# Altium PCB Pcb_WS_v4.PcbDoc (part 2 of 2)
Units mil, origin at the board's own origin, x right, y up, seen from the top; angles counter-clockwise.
Board outline 3890 x 3890 mil, 2 copper layers (Top Layer, Bottom Layer); 75 components, 61 nets, 248 pads, 370 vias.
Unrouted connection lines stored in the file: 31.
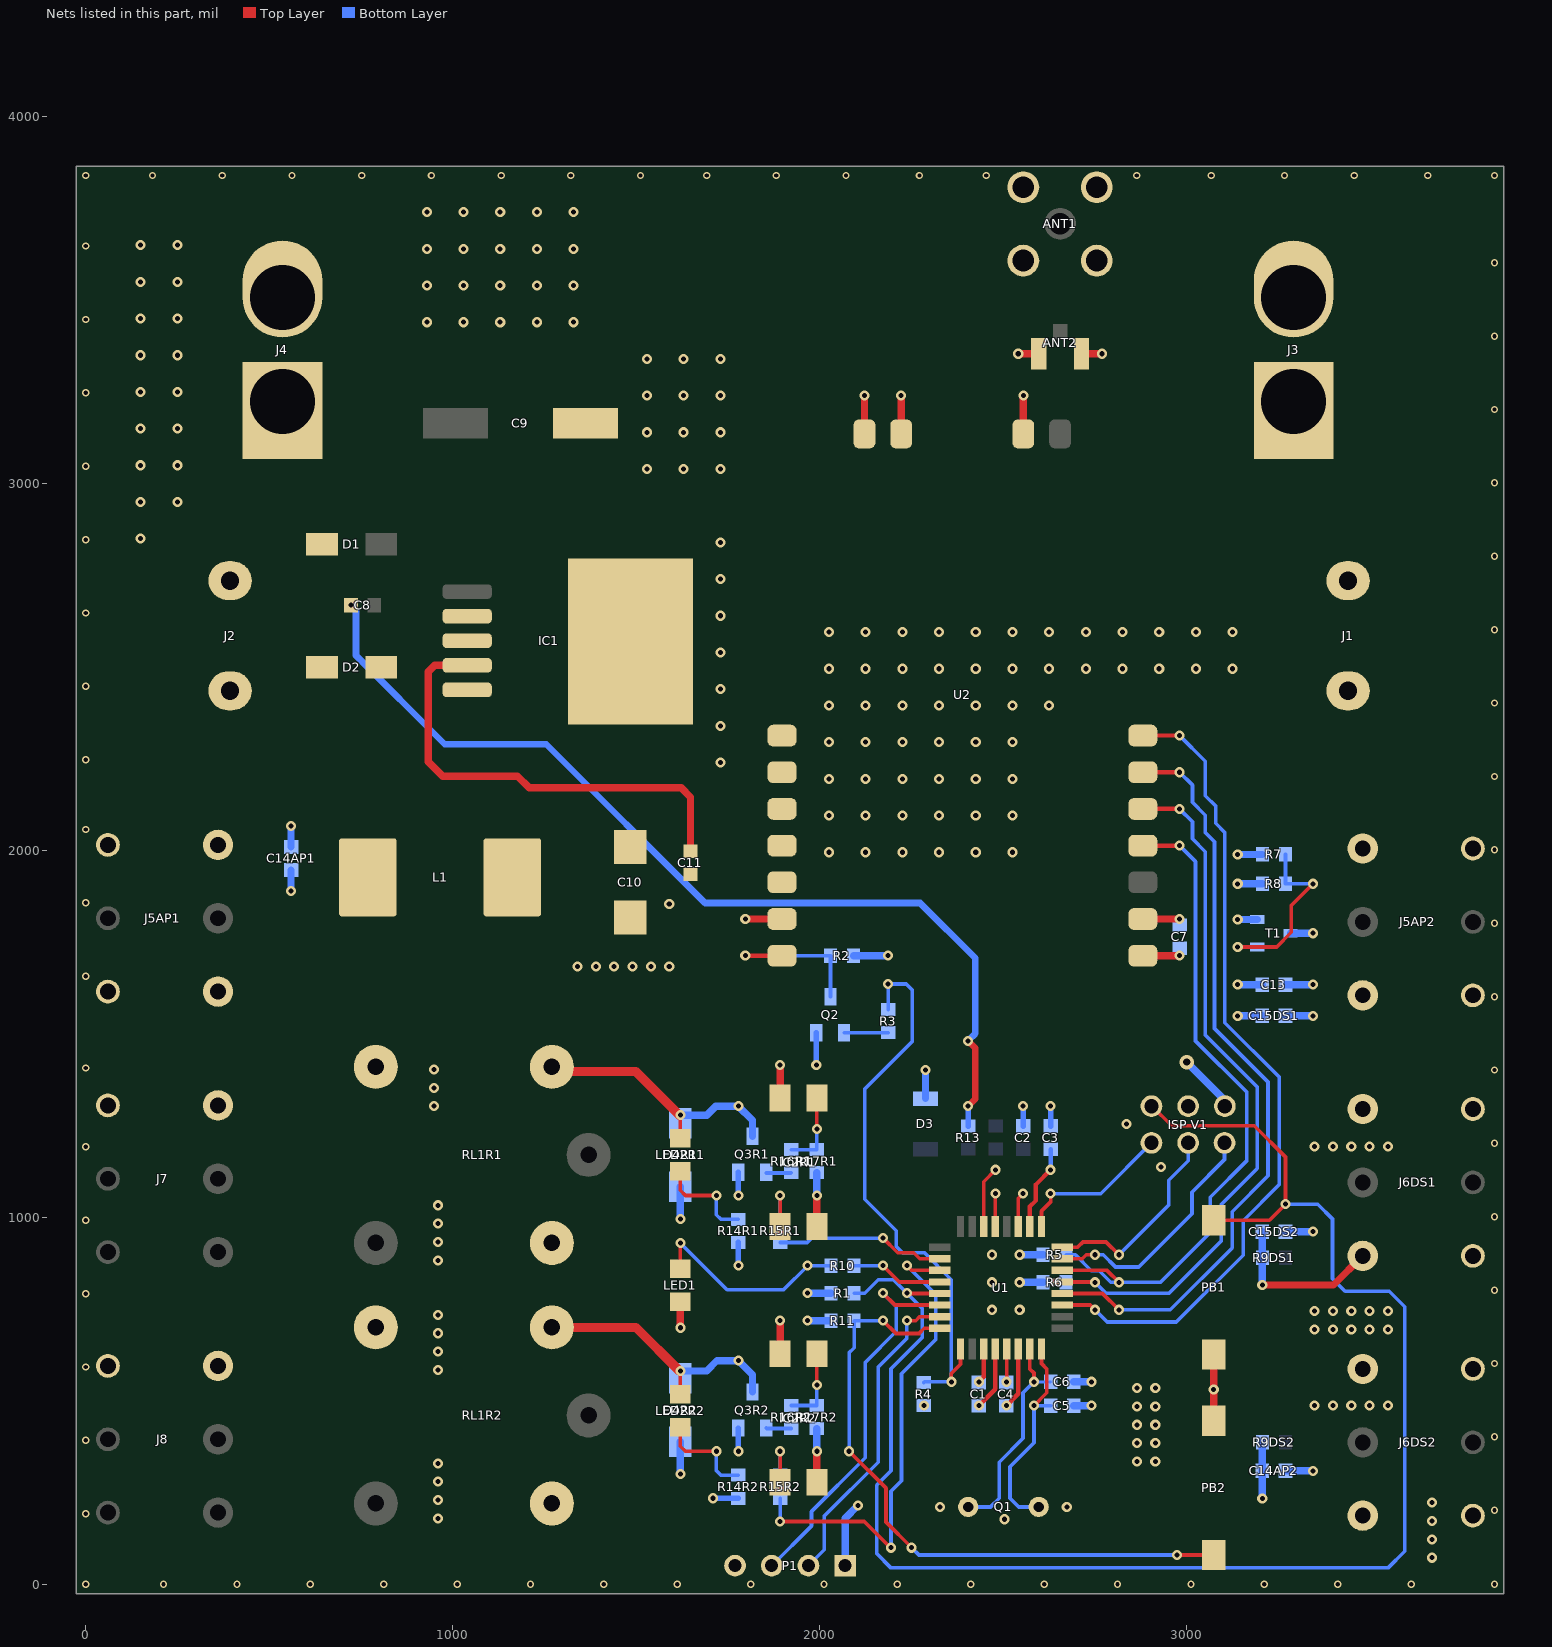
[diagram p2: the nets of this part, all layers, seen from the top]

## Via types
v1: diameter 27.56, hole 13.78, Top Layer to Bottom Layer, 293 vias
v2: diameter 20, hole 11.81, Top Layer to Bottom Layer, tented both sides, 76 vias
v3: diameter 39.37, hole 19.68, Top Layer to Bottom Layer, 1 vias

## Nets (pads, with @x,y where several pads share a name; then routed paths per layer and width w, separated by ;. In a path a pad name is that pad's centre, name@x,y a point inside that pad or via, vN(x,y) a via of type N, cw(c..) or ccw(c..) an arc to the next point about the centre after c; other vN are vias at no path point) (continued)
GND: "ISP V1.5" ANT1.2 ANT2.2 C1.2 C2.1 C3.2 C4.2 C5.2 C6.2 C7.2 C8.2 C9.2 C10.2 C11.2 C13.2 C14AP1.1 C14AP2.1 C15DS1.1 C15DS2.1 D2.2 D3.2 IC1.3 IC1.5 IC1.6 IC2R1.2 IC2R2.2 J2.1 J4.1 J5AP1.3 J5AP2.3 J6DS1.3 J6DS2.3 LED1.2 P1.4 PB1.2 PB2.2 Q2.2 Q3R1.2 Q3R2.2 R4.1 R5.2 R6.2 R7.1 R13.2 R17R1.1 R17R2.1 U1.3 U1.5 U1.21 U2.7 U2.9 U2.15 U2.16 U2.17 | length 5131
  Top Layer w9.84: U1.21@2479.06,975.59 2479.06,1064.06 v1(2480,1065) ; v1(2509.61,552.18) 2510.55,553.13 U1.5@2510.55,641.59
  Top Layer w12: v1(2434.61,552.18) 2447.56,565.13 U1.3@2447.56,641.59
  Top Layer w18: v1(2405,1303.39) 2425,1323.39 2425,1352.69 2425,1461 v1(2405,1481)
  Top Layer w20: v1(1620.86,699.46) LED1.2@1620.86,770 ; v1(1797.96,1813.49) U2.9@1897.96,1813.49 ; IC2R2.2@1992.86,278.06 v1(1992.86,362.87) ; IC2R1.2@1992.86,975.34 v1(1992.86,1060.15) ; U2.15@2122.76,3135.54 v1(2122.76,3240) ; U2.16@2222.76,3135.54 v1(2222.76,3240) ; v1(2541.92,3354) ANT2.2@2597.76,3354 ; U2.17@2555.84,3135.54 v1(2555.84,3240) ; ANT2.2@2713.91,3354 v1(2769.75,3354) ; U2.7@2881.43,1713.49 v1(2981.43,1713.49) ; PB2.2@3074.53,446.14 v1(3074.53,531.63) PB1.2@3074.53,626.54
  Bottom Layer w15: v1(1779.06,362.87) Q3R2.2@1779.06,426.1 ; v1(1779.06,1060.15) Q3R1.2@1779.06,1123.38 ; v1(1991.4,1416.07) Q2.2@1991.4,1503.58 ; R13.2@2405,1249.32 v1(2405,1303.39) ; C2.1@2555,1249.32 v1(2555,1303.39) ; C3.2@2630,1249.32 v1(2630,1303.39)
  Bottom Layer w18: v1(723,2669.78) 723,2668.46 737,2654.46 737,2531.74 978.74,2290 1255.5,2290 1688.5,1857 2274.34,1857 2425,1706.34 2425,1501.7 2405,1481.7 v1(2405,1481)
  Bottom Layer w20: C14AP1.1@560,2010 v1(560,2067.32) ; v1(1992.86,362.87) R17R2.1@1992.86,424.74 ; v1(1992.86,1060.15) R17R1.1@1992.86,1122.02 ; D3.2@2289.08,1324.12 v1(2289.08,1401.78) ; v1(2545.81,823.39) R6.2@2609.67,823.39 ; v1(2545.81,898.39) R5.2@2609.67,898.39 ; C5.2@2693.3,487.18 v1(2741.21,487.18) ; C6.2@2693.3,552.18 v1(2741.21,552.18) ; v1(3140,1549.46) C15DS1.1@3207.01,1549.46 ; v1(3140,1634.46) C13.2@3207.01,1634.46 ; v1(3140,1989.46) R7.1@3207.01,1989.46 ; C14AP2.1@3270,309.46 v1(3345,309.46) ; C15DS2.1@3270,961.31 v1(3345,961.31)
  other v1: 2504.75,177.52 960,180 2328.96,210.91 2674.14,211.33 960,230 960,280 960,330 2865.32,335.02 2915.32,335.02 2865.32,385.02 2915.32,385.02 2865.32,435.02 2915.32,435.02 2865.32,485.02 2915.32,485.02 2284.61,487.18 3349.51,487.18 3399.51,487.18 3449.51,487.18 3499.51,487.18 3549.51,487.18 2865.32,535.02 2915.32,535.02 960,584.51 960,634.51 960,684.51 3349.51,694.61 3399.51,694.61 3449.51,694.61 3499.51,694.61 3549.51,694.61 960,734.51 3349.51,744.61 3399.51,744.61 3449.51,744.61 3499.51,744.61 3549.51,744.61 2470.81,748.39 2545.81,748.39 2470.81,823.39 960,883.21 2470.81,898.39 960,933.21 960,983.21 960,1033.21 2931.35,1137.33 3349.51,1193.65 3399.51,1193.65 3449.51,1193.65 3499.51,1193.65 3549.51,1193.65 2836.6,1254.69 950,1303.39 950,1353.39 950,1403.39 1340.62,1683.72 1390.62,1683.72 1440.62,1683.72 1490.62,1683.72 1540.62,1683.72 1590.62,1683.72 1590.62,1854.25 2026.06,1995.48 2126.06,1995.48 2226.06,1995.48 2326.06,1995.48 2426.06,1995.48 2526.06,1995.48 2026.06,2095.48 2126.06,2095.48 2226.06,2095.48 2326.06,2095.48 2426.06,2095.48 2526.06,2095.48 2026.06,2195.48 2126.06,2195.48 2226.06,2195.48 2326.06,2195.48 2426.06,2195.48 2526.06,2195.48 1730,2240 2026.06,2295.48 2126.06,2295.48 2226.06,2295.48 2326.06,2295.48 2426.06,2295.48 2526.06,2295.48 1730,2340 2026.06,2395.48 2126.06,2395.48 2226.06,2395.48 2326.06,2395.48 2426.06,2395.48 2526.06,2395.48 2626.06,2395.48 1730,2440 2026.06,2495.48 2126.06,2495.48 2226.06,2495.48 2326.06,2495.48 2426.06,2495.48 2526.06,2495.48 2626.06,2495.48 2726.06,2495.48 2826.06,2495.48 2926.06,2495.48 3026.06,2495.48 3126.06,2495.48 1730,2540 2026.06,2595.48 2126.06,2595.48 2226.06,2595.48 2326.06,2595.48 2426.06,2595.48 2526.06,2595.48 2626.06,2595.48 2726.06,2595.48 2826.06,2595.48 2926.06,2595.48 3026.06,2595.48 3126.06,2595.48 1730,2640 1730,2740 1730,2840 150,2850 150,2950 250,2950 1530,3040 1630,3040 1730,3040 150,3050 250,3050 1530,3140 1630,3140 1730,3140 150,3150 250,3150 1530,3240 1630,3240 1730,3240 150,3250 250,3250 1530,3340 1630,3340 1730,3340 150,3350 250,3350 930,3440 1030,3440 1130,3440 1230,3440 1330,3440 150,3450 250,3450 930,3540 1030,3540 1130,3540 1230,3540 1330,3540 150,3550 250,3550 930,3640 1030,3640 1130,3640 1230,3640 1330,3640 150,3650 250,3650 930,3740 1030,3740 1130,3740 1230,3740 1330,3740
  other v2: 0,0 212.5,0 412.5,0 612.5,0 812.5,0 1012.5,0 1212.5,0 1412.5,0 1612.5,0 1812.5,0 2012.5,0 2212.5,0 2412.5,0 2612.5,0 2812.5,0 3012.5,0 3212.5,0 3412.5,0 3612.5,0 3840,0 0,192.5 3840,202 0,392.5 3840,402 0,592.5 3840,602 0,792.5 3840,802 0,992.5 3840,1002 0,1192.5 3840,1202 3840,1402 0,1407.5 3840,1602 0,1657.5 3840,1802 0,1857.5 3840,2002 0,2057.5 3840,2202 0,2247.5 3840,2402 0,2447.5 3840,2602 0,2647.5 3840,2802 0,2847.5 3840,3002 0,3047.5 3840,3202 0,3247.5 3840,3402 0,3447.5 3840,3602 0,3647.5 0,3840 182.5,3840 372.5,3840 562.5,3840 752.5,3840 942.5,3840 1132.5,3840 1322.5,3840 1512.5,3840 1692.5,3840 1882.5,3840 2072.5,3840 2272.5,3840 2455,3840 2865,3840 3067.5,3840 3267.5,3840 3457.5,3840 3657.5,3840 3840,3840
GND-SOLAR: J1.2 J3.1
LED: R10.1 U1.28 | length 251.5
  Top Layer w10: v1(2173.39,868.79) 2217.84,824.34 U1.28@2327.8,824.34
  Bottom Layer w10: R10.1@2094.71,868.79 v1(2173.39,868.79)
M0: U1.11 U2.1 | length 2257
  Top Layer w10: U1.11@2661.8,761.35 2738.26,761.35 v1(2751.21,748.39)
  Top Layer w12: U2.1@2881.43,2313.49 v1(2981.43,2313.49)
  Bottom Layer w10: v1(2751.21,748.39) 2784.61,715 2972.76,715 3155,897.24 3155,991.44 3252.78,1089.22 3252.78,1383.22 3105,1531 3105,2049.32 3079.99,2074.33 3079.99,2121.3 3051.66,2149.62 3051.66,2243.26 v1(2981.43,2313.49)
M1: U1.12 U2.2 | length 2088.2
  Top Layer w10: U1.12@2661.8,792.84 2771.76,792.84 v1(2816.21,748.39)
  Top Layer w12: U2.2@2881.43,2213.49 v1(2981.43,2213.49)
  Bottom Layer w10: v1(2816.21,748.39) 2956.3,748.39 3125,917.1 3125,1015.78 3222.63,1113.4 3222.63,1369.3 3076.84,1515.08 3076.84,2024.15 3051.66,2049.32 3051.66,2096.29 3016.54,2131.41 3016.54,2178.37 v1(2981.43,2213.49)
MISO: "ISP V1.2" U1.16 | length 558.1
  Top Layer w10: U1.16@2661.8,918.83 2703.65,918.83 2718.21,933.39 2781.21,933.39 v1(2816.21,898.39)
  Bottom Layer w10: v1(2816.21,898.39) 2951.74,1033.92 2951.74,1101.42 3005,1154.68 3005,1203.39
MOSI: "ISP V1.3" U1.15 | length 662
  Top Layer w10: U1.15@2661.8,887.33 2716.13,887.33 2727.19,898.39 v1(2751.21,898.39)
  Bottom Layer w10: v1(2751.21,898.39) 2773.31,898.39 2806.71,865 2870.12,865 3015.32,1010.2 3015.32,1069.12 3104,1157.81 3104,1203.39
NetD2_1: D2.1 IC1.2 L1.1
NetD4R1_2: D4R1.2 LED2R1.2 Q3R1.3 RL1R1.4 | length 728.5
  Top Layer w10: LED2R1.2@1620.86,1215.54 v1(1620.86,1278.81)
  Top Layer w25: RL1R1.4@1270.86,1397.82 1499.46,1397.82 v1@1618.47,1278.81
  Bottom Layer w20: D4R1.2@1618.47,1278.81 v1(1620.86,1278.81) 1692.53,1278.81 1717.12,1303.39 v1(1779.06,1303.39) 1817.66,1264.8 Q3R1.3@1817.66,1221.8
NetD4R2_2: D4R2.2 LED2R2.2 Q3R2.3 RL1R2.4 | length 734
  Top Layer w10: LED2R2.2@1620.86,518.26 v1(1620.86,581.53)
  Top Layer w25: RL1R2.4@1270.86,700.54 1499.46,700.54 v1@1618.47,581.53
  Bottom Layer w20: D4R2.2@1618.47,581.53 1692.53,581.53 1721,610 v1(1779.06,610) 1817.66,571.4 Q3R2.3@1817.66,524.52
NetIC2R1_1: IC2R1.1 R15R1.2 | length 149.9
  Top Layer w10: IC2R1.1@1892.86,975.34 v1(1892.86,1060.15)
  Bottom Layer w10: R15R1.2@1892.86,995.01 v1(1892.86,1060.15)
NetIC2R2_1: IC2R2.1 R15R2.2 | length 149.9
  Top Layer w10: IC2R2.1@1892.86,278.06 v1(1892.86,362.87)
  Bottom Layer w10: R15R2.2@1892.86,297.73 v1(1892.86,362.87)
NetLED1_1: LED1.1 R10.2 | length 561.5
  Top Layer w10: LED1.1@1620.86,860 v1(1620.86,930.54)
  Bottom Layer w10: v1(1620.86,930.54) 1748.4,803 1902.07,803 v1(1967.86,868.79) R10.2@2031.72,868.79
NetLED2R1_1: LED2R1.1 R14R1.2 | length 273.2
  Top Layer w10: LED2R1.1@1620.86,1125.54 1620.86,1074.14 1634.86,1060.15 v1(1719.06,1060.15)
  Bottom Layer w10: v1(1719.06,1060.15) 1719.06,1007.6 1731.65,995.01 R14R1.2@1779.06,995.01
NetLED2R2_1: LED2R2.1 R14R2.2 | length 273.2
  Top Layer w10: LED2R2.1@1620.86,428.26 1620.86,376.86 1634.86,362.87 v1(1719.06,362.87)
  Bottom Layer w10: v1(1719.06,362.87) 1719.06,310.32 1731.65,297.73 R14R2.2@1779.06,297.73
NetQ2_1: Q2.1 R3.2 | length 119.9
  Bottom Layer w10: Q2.1@2067.2,1503.8 R3.2@2187.06,1503.8
NetQ3R1_1: Q3R1.1 R16R1.2 | length 68.4
  Bottom Layer w10: Q3R1.1@1854.86,1121.01 1921.85,1121.01 R16R1.2@1922.86,1122.02
NetQ3R2_1: Q3R2.1 R16R2.2 | length 68.7
  Bottom Layer w10: Q3R2.1@1854.86,426.31 1856.43,424.74 R16R2.2@1922.86,424.74
NetR7_2: R7.2 R8.2 T1.1 | length 527.4
  Top Layer w10: v1(3140,1737.33) 3246.14,1737.33 3286.13,1777.32 3286.13,1850.59 v1(3345,1909.46)
  Bottom Layer w10: v1(3140,1737.33) T1.1@3193.23,1737.33 ; R7.2@3270,1989.46 R8.2@3270,1909.46 v1(3345,1909.46)
NetU1_19: U1.19 | length 94.8
  Top Layer w10: U1.19@2542.05,975.59 2542.05,1052.05 v1(2555,1065)
NetU1_22: U1.22 | length 167.8
  Top Layer w10: U1.22@2447.56,975.59 2447.56,1097.56 v1(2480,1130)
NetU2_10: U2.10
NetU2_11: U2.11
NetU2_12: U2.12
NetU2_13: U2.13
NetU2_14: U2.14
OPEN1: J7.1 RL1R1.3
OPEN2: J8.1 RL1R2.3
P5V-Main: "ISP V1.6" C1.1 C3.1 C4.1 C7.1 C10.1 C11.1 D4R1.1 D4R2.1 IC1.4 IC2R1.4 IC2R2.4 L1.2 P1.1 R1.1 R2.2 R8.1 R11.1 R14R1.1 R14R2.1 RL1R1.5 RL1R2.5 T1.2 U1.4 U1.6 U1.18 U2.6 | length 3107.7
  Top Layer w12: v1(2434.61,487.18) 2479.06,531.63 U1.4@2479.06,641.59 ; v1(2509.61,487.18) 2542.05,519.62 U1.6@2542.05,641.59 ; U1.18@2573.54,975.59 2573.54,1029.92 2590,1046.38 2590,1090 v1(2630,1130)
  Top Layer w20: IC1.4@1040.04,2505.03 952.03,2505.03 934,2487 934,2242.02 973.02,2203 1177,2203 1209.23,2170.77 1623.39,2170.77 1648.55,2145.61 C11.1@1648.55,1998.5 ; IC2R2.4@1892.86,628.46 v1(1892.86,718.79) ; IC2R1.4@1892.86,1325.74 v1(1892.86,1416.07) ; U2.6@2881.43,1813.49 v1(2981.43,1813.49)
  Bottom Layer w12: v1(2630,1130) C3.1@2630,1186.32
  Bottom Layer w15: v1(1710,234.74) R14R2.1@1779.06,234.74 ; v1(1779.06,868.79) R14R1.1@1779.06,932.02
  Bottom Layer w20: v1(1620.86,300.47) D4R2.1@1620.86,388.39 ; v1(1620.86,996.01) D4R1.1@1620.86,1083.93 ; v1(1967.86,718.79) R11.1@2031.72,718.79 ; v1(1967.86,793.79) R1.1@2031.72,793.79 ; P1.1@2070,51 2070,180.55 v1(2105,215.55) ; R2.2@2092.99,1713.49 v1(2187.06,1713.49) ; v3(3001.21,1423.39) 3105,1319.6 3105,1303.39 ; v1(3140,1812.14) T1.2@3193.23,1812.14 ; v1(3140,1909.46) R8.1@3207.01,1909.46
P5V-SEN: C13.1 C14AP1.2 C14AP2.2 C15DS1.2 C15DS2.2 J5AP1.1 J5AP2.1 J6DS1.1 J6DS2.1 R9DS1.2 R9DS2.2 T1.3 | length 873.8
  Top Layer w20: v1(3207.01,815.77) 3401.09,815.77 J6DS1.1@3480.86,895.54
  Bottom Layer w20: v1(560,1889.69) C14AP1.2@560,1947.01 ; v1(3207.01,234.46) C14AP2.2@3207.01,309.46 R9DS2.2@3207.01,387.26 ; v1(3207.01,815.77) R9DS1.2@3207.01,890.77 C15DS2.2@3207.01,961.31 ; C15DS1.2@3270,1549.46 v1(3345,1549.46) ; C13.1@3270,1634.46 v1(3345,1634.46) ; T1.3@3283.78,1774.74 v1(3345,1774.74)
  other v1: 3670,72.74 3670,122.74 3670,172.74 3670,222.74
P12V-BAT: D1.2 J2.2 J4.2
P16V-SOLAR: J1.1 J3.2
RESET-E32: R3.1 R4.2 U1.1 | length 1571.2
  Top Layer w10: v1(2359.61,552.18) 2359.61,574.79 2384.57,599.75 U1.1@2384.57,641.59
  Bottom Layer w9.84: R3.1@2187.06,1566.79 v1(2187.06,1636.26)
  Bottom Layer w10: v1(2187.06,1636.26) 2236.59,1636.26 2252.53,1620.32 2252.53,1478.75 2123.79,1350.01 2123.79,1049.97 2209.61,964.15 2209.61,920.77 2226.6,903.79 2286.16,903.79 2359.61,830.34 v1(2359.61,552.18) 2286.61,552.18 R4.2@2284.61,550.17
RL-CT-QR1: IC2R1.3 R16R1.1 R17R1.2 | length 210.7
  Top Layer w10: v1(1992.86,1240.93) IC2R1.3@1992.86,1325.74
  Bottom Layer w10: R16R1.1@1922.86,1185.01 R17R1.2@1992.86,1185.01 v1(1992.86,1240.93)
RL-CT-QR2: IC2R2.3 R16R2.1 R17R2.2 | length 210.7
  Top Layer w10: v1(1992.86,543.65) IC2R2.3@1992.86,628.46
  Bottom Layer w10: R16R2.1@1922.86,487.73 R17R2.2@1992.86,487.73 v1(1992.86,543.65)
RL-CTL1: R15R1.1 U1.26 | length 463.2
  Top Layer w10: v1(2173.39,943.79) 2213.39,903.79 2257.02,903.79 2273.48,887.33 U1.26@2327.8,887.33
  Bottom Layer w10: R15R1.1@1892.86,932.02 1966.67,932.02 1978.44,943.79 v1(2173.39,943.79)
RL-CTL2: R15R2.1 U1.27 | length 1341.3
  Top Layer w10: v1(1892.86,171.51) 2122.09,171.51 2193.6,100 v1(2195,100) ; v1(2238.39,868.79) 2251.35,855.83 U1.27@2327.8,855.84
  Bottom Layer w10: v1(1892.86,171.51) R15R2.1@1892.86,234.74 ; v1(2195,100) 2195,253.8 2223.78,282.58 2223.78,573.78 2316.63,666.63 2316.63,790.55 v1(2238.39,868.79)
RST-E32: Q2.3 R2.1 U2.8 | length 443.5
  Top Layer w12: v1(1797.96,1713.49) U2.8@1897.96,1713.49
  Bottom Layer w10: v1(1797.96,1713.49) R2.1@2030,1713.49 Q2.3@2030,1602.01
RST_MCU: "ISP V1.4" PB1.1 R1.2 U1.29 | length 4483.3
  Top Layer w10: v1(2238.39,793.79) 2239.34,792.84 U1.29@2327.8,792.84 ; 2905,1303.39 2906.61,1303.39 2960,1250 3185,1250 3270,1165 v1(3270,1036.31) 3226.37,992.69 PB1.1@3074.53,992.69
  Bottom Layer w10: R1.2@2094.71,793.79 2123.79,793.79 2160,830 2202.18,830 v1(2238.39,793.79) 2279.79,752.39 2279.79,672.4 2195,587.61 2195,309.71 2155.91,270.62 2155.91,84.09 2195,45 3549.61,45 3595.18,90.57 3595.18,756.82 3553.32,798.68 3432.64,798.68 3398.54,832.78 3398.54,996 3358.23,1036.31 v1(3270,1036.31)
RXD-E32: R6.1 U1.13 U2.3 | length 1989.3
  Top Layer w10: U1.13@2661.8,824.34 2750.27,824.34 v1(2751.21,823.39)
  Top Layer w12: U2.3@2881.43,2113.49 v1(2981.43,2113.49)
  Bottom Layer w10: R6.1@2672.66,823.39 v1(2751.21,823.39) 2780.82,793.79 2952.86,793.79 3095,935.92 3095,1035.54 3193.23,1133.77 3193.23,1355.88 3051.66,1497.45 3051.66,1997.11 3016.54,2032.22 3016.54,2078.37 v1(2981.43,2113.49)
RXM: P1.3 U1.30 | length 1066.3
  Top Layer w10: v1(2173.39,793.79) 2205.84,761.35 U1.30@2327.8,761.35
  Bottom Layer w10: P1.3@1870,51 1978.44,159.44 1978.44,198.44 2125,345 2125,605 2209.61,689.61 2209.61,757.57 v1(2173.39,793.79)
SCK: "ISP V1.1" U1.17 | length 432.1
  Top Layer w10: U1.17@2605.04,975.59 2605.04,1017.43 2630,1042.39 v1(2630,1065)
  Bottom Layer w10: v1(2630,1065) 2766.61,1065 2905,1203.39
TXD-E32: R5.1 U1.14 U2.4 | length 1919.5
  Top Layer w10: U1.14@2661.8,855.84 2783.77,855.83 v1(2816.21,823.39)
  Top Layer w12: U2.4@2881.43,2013.49 v1(2981.43,2013.49)
  Bottom Layer w10: R5.1@2672.66,898.39 2697.59,898.39 2740.98,855 2762.28,855 2793.89,823.39 v1(2816.21,823.39) 2929.61,823.39 3065,958.79 3065,1055 3165,1155 3165,1341 3025,1481 3025,1969.92 v1(2981.43,2013.49)
TXM: P1.2 U1.31 | length 873
  Top Layer w10: v1(2238.39,718.79) 2262.41,718.79 2273.48,729.85 U1.31@2327.8,729.85
  Bottom Layer w10: P1.2@1970,51 2013.25,94.25 2013.25,186.2 2160,332.95 2160,592.5 2238.39,670.89 v1(2238.39,718.79)
WAKE: PB2.1 R11.2 U1.32 | length 1780.3
  Top Layer w10: v1(2080.83,362.87) 2181.2,262.5 2181.2,170.15 v1(2251.35,100) ; v1(2173.39,718.79) 2208.39,683.79 2271.39,683.79 2285.96,698.35 U1.32@2327.8,698.35 ; v1(2975,80) PB2.1@3074.53,80
  Bottom Layer w10: v1(2080.83,362.87) 2080.83,631.12 2094.71,645 R11.2@2094.71,718.79 v1(2173.39,718.79) ; v1(2251.35,100) 2271.35,80 v1(2975,80)
XTAL1: C6.1 Q1.1 U1.7 | length 590.6
  Top Layer w10: U1.7@2573.54,641.59 2573.54,587.26 2584.61,576.2 v1(2584.61,552.18)
  Bottom Layer w8: v1(2584.61,552.18) C6.1@2630.31,552.18
  Bottom Layer w10: Q1.1@2405.49,211.12 2466.32,211.12 2489.95,234.74 2489.95,333.04 2555,398.09 2555,522.58 v1(2584.61,552.18)
XTAL2: C5.1 Q1.2 U1.8 | length 587.9
  Top Layer w10: v1(2584.61,487.18) 2619.61,522.18 2619.61,587.26 2605.04,601.83 U1.8@2605.04,641.59
  Bottom Layer w10: Q1.2@2597.61,211.12 2543.17,211.12 2519.55,234.74 2519.55,320.77 2584.61,385.83 v1(2584.61,487.18) C5.1@2630.31,487.18

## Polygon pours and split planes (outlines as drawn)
GND on Top Layer "GND_L01_P040" (solid, pour order 40): 770,1271.63 900,1141.63 900,969.62 900,10 1030,10 1030,1470 539.28,1470 460.95,1551.25 460.95,1730 10,1730 10,1403.39 508.23,1403.39 640,1271.63
GND on Top Layer "GND_L01_P039" (solid, pour order 39): 2906.03,595.06 2712.18,595.06 2712.18,295 2960,295 3830,295 3830,2213.49 3175,2213.49 3175,2650 1975,2650 1975,1943 3216,1943 3216,1788 3076.84,1788 3076.84,1395.95 2816.21,1395.95 2816.21,1106.63 2906.03,1106.63
P5V-Main on Top Layer "P5V-MAIN_L01_P035" (solid, pour order 35): 2905,595.06 2711.81,595.06 2711.81,295 2632.31,295 2405.49,295 2405.49,151.44 1162.95,151.44 1162.95,1575 1295,1575 1295,1625 1634.86,1625 1634.86,1875 1690,1875 1690,1929.85 3216,1929.85 3216,1788 3076.84,1788 3076.84,1395.95 2799.07,1395.95 2799.07,1106.63 2905,1106.63
P5V-SEN on Top Layer "P5V-SEN_L01_P031" (solid, remove dead copper, pour order 31): 2597.61,267.76 2597.61,125 2150,125 2123.56,151.44 1162.95,151.44 1162.95,1575 590.98,1575 590.98,2085 565.99,2110 55,2110 15,2070 15,1947.49 35.49,1927 423.78,1927 459.78,1891 459.78,1552.12 541.9,1470 960,1470 1030,1400 1030,35.49 2121.6,35.49 2147.09,10 2950,10 2950,135.48 2995.48,135.48 3139.52,135.48 3139.52,10 3265,10 3830,10 3830,267.76
GND on Top Layer "GND_L01_P037" (solid, pour order 37): 1975,3804.51 1975,2750 3000,2750 3000,3804.51
GND on Top Layer "GND_L01_P027" (solid, remove dead copper, pour order 27): 1690,1875 1690,1967 1825,1967 1825,2650 1875,2650 1875,3830 10,3830 10,2225 625,2225 625,1625 1625,1625 1625,1875
GND-SOLAR on Top Layer "GND-SOLAR_L01_P028" (solid, pour order 28): 3275,2750 3100,2750 3100,3830 3830,3830 3830,2285 3275,2285
no net on Top Layer "Top Layer-No Net" (solid, shelved, pour order 14): 1035.77,4959.95
no net on Top Layer "AutoNaming" (solid, shelved, pour order 22): -54.14,125.54
no net on Top Layer "AutoNaming" (solid, shelved, pour order 26): -54.14,125.54
GND on Bottom Layer "GND-Bottom" (solid, remove dead copper, pour order 38): 10,3830 1875,3830 1875,2650 3175,2650 3175,2215 3830,2215 3830,1805.54 3340.37,1805.54 3340.37,1402 3605,1402 3605,261.82 3605,10 10,10
P5V-SEN on Bottom Layer "P5V-SEN_L02_P030" (solid, remove dead copper, pour order 30): 3340.37,1414.51 3352.88,1402 3585.35,1402 3605,1382.35 3605,311.82 3605,10 3820,10 3820,1655 3805,1670 3407.69,1670 3392.69,1685 3392.69,1805.54 3340.37,1805.54
GND on Bottom Layer "GND_L02_P033" (solid, pour order 33): 1975,3804.51 1975,2750 3000,2750 3000,3804.51
P16V-SOLAR on Bottom Layer "P16V-SOLAR_L02_P029" (solid, pour order 29): 3275,2750 3100,2750 3100,3837.5 3837.5,3837.5 3837.5,2285 3275,2285

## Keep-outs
Bottom Layer:
  region: 3839.91,2216.96
Keep-Out Layer:
  the board outline again, w5

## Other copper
Top Layer:
  pour cut-out: 3040.36,489.6 3108,489.6 3108,402.6 3040.36,402.6
  pour cut-out: 3040.36,670 3108,670 3108,583 3040.36,583
  pour cut-out: 2921.04,1743.27 2921.04,1683.72 2841.81,1683.72 2841.81,1743.27
  region net GND: 2654.54,280.26 2668.29,274.56 2680.67,266.29 2691.2,255.77 2699.47,243.39 2705.17,229.63 2708.07,215.03 2708.07,207.58 2708.07,200.83 2705.44,187.58 2700.27,175.1 2692.76,163.86 2683.21,154.31 2671.97,146.81 2659.49,141.64 2646.24,139 2362.87,139 2348.35,141.89 2334.67,147.55 2322.37,155.78 2311.9,166.24 2303.68,178.55 2298.01,192.23 2295.12,206.74 2295.12,214.15 2295.12,220.94 2297.78,234.28 2302.98,246.84 2310.53,258.14 2320.15,267.76 2331.45,275.31 2344.01,280.51 2357.35,283.17 2639.93,283.17 hole: 2597.61,249 2587.81,247.71 2578.67,243.93 2570.83,237.91 2564.81,230.06 2561.02,220.92 2559.73,211.12 2561.02,201.31 2564.81,192.18 2570.83,184.33 2578.67,178.31 2587.81,174.53 2597.61,173.24 2607.42,174.53 2616.56,178.31 2624.4,184.33 2630.42,192.18 2634.21,201.31 2635.5,211.12 2634.21,220.92 2630.42,230.06 2624.4,237.91 2616.56,243.93 2607.42,247.71 hole: 2405.49,249 2395.68,247.71 2386.55,243.93 2378.7,237.91 2372.68,230.06 2368.9,220.92 2367.61,211.12 2368.9,201.31 2372.68,192.18 2378.7,184.33 2386.55,178.31 2395.68,174.53 2405.49,173.24 2415.29,174.53 2424.43,178.31 2432.28,184.33 2438.3,192.18 2442.08,201.31 2443.37,211.12 2442.08,220.92 2438.3,230.06 2432.28,237.91 2424.43,243.93 2415.29,247.71
  region net GND: 2385,920 2385,698.35 2605.04,698.35 2605.04,918.83
  pour cut-out: 2575,3400 2736.22,3400 2736.22,3309.04 2575,3309.04
  pour cut-out: 2526.06,3175.16 2585.61,3175.16 2585.61,3095.92 2526.06,3095.92
  pour cut-out: 2192.99,3175.16 2252.54,3175.16 2252.54,3095.92 2192.99,3095.92
  pour cut-out: 2092.99,3175.16 2152.54,3175.16 2152.54,3095.92 2092.99,3095.92
  pour cut-out: 2921.04,1843.27 2921.04,1783.72 2841.81,1783.72 2841.81,1843.27
  pour cut-out: 2880,1855
  pour cut-out: 2880,1855
  pour cut-out: 2359.57,943.83 2630.04,943.83 2630.04,673.35 2359.57,673.35
  pour cut-out: 1849.32,329.48 2036.4,329.48 2036.4,226.65 1849.32,226.65
  pour cut-out: 2036.4,1377.15 2036.4,1274.32 1855,1274.32 1855,1377.15
  pour cut-out: 1578.36,1255.54 1663.36,1255.54 1663.36,1085.54 1578.36,1085.54
  pour cut-out: 1578.36,900 1663.36,900 1663.36,730 1578.36,730
  pour cut-out: 1663.36,558.26 1578.36,558.26 1578.36,388.26 1663.36,388.26
  pour cut-out: 2036.4,577.04 2036.4,679.87 1855,679.87 1855,577.04
  pour cut-out: 2584.61,472.76 2584.61,552.18 2345.19,552.18 2345.19,472.76
  pour cut-out: 2158.98,718.79 2238.39,718.79 2238.39,958.21 2158.98,958.21
  pour cut-out: 2830.63,898.39 2751.21,898.39 2751.21,658.97 2830.63,658.97
  pour cut-out: 2405,1144.42 2405,1065 2644.42,1065 2644.42,1144.42
  pour cut-out: 2359.57,943.83
  region net BAT-VSEN: 760,2647.5 769.5,2638 880,2638 927,2685 1102.5,2685 1115,2697.5 1115,3217.01 1092.01,3240 828.72,3240 760,3171.28 760,2920 734.51,2894.51 734.51,2762.55 760,2737.06
  region net P12V-BAT: 265,2844.68 360.86,2940.54 360.86,3332.7 393.16,3365 684.8,3365 734.51,3315.29 734.51,2943.37 707.5,2916.36 707.5,2765.64 683.42,2741.55 580.99,2741.55 536.41,2696.98 536.41,2639.22 505.56,2608.38 306.95,2608.38 265,2650.33
  pour cut-out: 855,2157 1075,2157 1295,2157 1295,1625 665,1625 665,2157
  pour cut-out: 752.21,2386.28 752.21,2735 1140.49,2735 1140.49,2386.28
  region net P5V-Main: 1075,1815 1095,1795 1175,1795 1295,1795 1335,1835 1335,1915 1365,1945 1405,1945 1555,1945 1585,1975 1807.96,1975 1817.96,1985 1817.96,2085 1807.96,2095 1132.5,2095 1075,2037.5 1075,2015.54
  region net NetD2_1: 932,2660 1101,2660 1108.75,2652.25 1108.75,2624.75 1102,2618 963,2618 901,2556 901,2203 855,2157 855,1825 840,1810 690,1810 665,1835 665,2205.55 750,2290.55 750,2598.75 769.25,2618 890,2618
  region net GND: -10,-10 3850,-10.18 3850,3850.04 2865,3850 2865,3830 3830,3830 3830,10 10,10 10,3830 2455,3830 2455,3850 -10,3850
  region: -25,3865
  region: 957.01,1081.11
  pour cut-out: 3895.54,1395.95
  pour cut-out: 3895.54,1395.95
  region: 285.86,2865.54
Bottom Layer:
  pour cut-out: 3174.29,421.95 3302.72,421.95 3302.72,274.78 3173.31,274.78
  pour cut-out: 525.32,2043.7 525.32,1925 590.98,1925 590.98,2043.7
  pour cut-out: 2596.61,586.86 2596.61,452.49 2766.4,452.49 2766.4,586.86
  pour cut-out: 1999,943.79 2127.43,943.79 2127.43,684.1 1999,684.1
  pour cut-out: 2946.74,1685 3004.61,1685 3004.61,1830.2 2946.74,1830.2
  pour cut-out: 625,1475 898.39,1475 898.39,1240.93 1435,1240.93 1435,1095 910,1095 910,530.93 1435,530.93 1435,385 910,385 910,10 10,10 10,1385 625,1385
  pour cut-out: 2705.38,788.71 2520.32,788.71 2520.32,933.08 2705.38,933.08
  pour cut-out: 2664.68,1152.62 2664.68,1324.59 2370.32,1324.59 2370.32,1152.62
  pour cut-out: 2333.52,1294.43 2244.7,1294.43 2244.7,1419.61 2333.52,1419.61
  pour cut-out: 2027.54,1034.66 1957.54,1034.66 1957.54,1217.73 2027.54,1217.73
  pour cut-out: 1805.79,1130 1805.79,1037.2 1752.33,1037.2 1752.33,1157 1805.79,1157
  pour cut-out: 3175.39,856.09 3302.72,856.09 3302.72,996 3175.39,996
  pour cut-out: 2020,1515 2020,1393.13 1964.67,1393.13 1964.67,1537.2 2020,1537.2
  pour cut-out: 1805.79,464.93 1805.79,339.93 1752.33,339.93 1752.33,464.93
  pour cut-out: 2027.54,520.45 2027.54,337.38 1957.54,337.38 1957.54,520.45
  pour cut-out: 3299.51,1669.15 3299.51,1514.78 3125.39,1514.78 3125.39,1669.15
  pour cut-out: 3302.72,2024.15 3302.72,1874.78 3125.39,1874.78 3125.39,2024.15
  pour cut-out: 2539.29,453.48 2242.62,453.48 2242.62,578.87 2539.29,578.87
  region net CLOSE1: 650,965 700,1015 862.6,1015 875,1002.6 875,865 865,855 34,855 21.5,867.51 21.5,955 31.5,965
  region net OPEN1: 33,1385 525,1385 615,1475 865,1475 875,1465 875,1335 865,1325 625,1325 545,1245 33,1245 22,1256 22,1374
  region net COM1: 30.75,1165 578.58,1165 654.51,1240.93 1415.87,1240.93 1435,1221.8 1435,1108.54 1421.46,1095 663.57,1095 613.58,1045 35,1045 20,1060 20,1154.25
  region net GND: -10,-10 3850,-10.18 3850,3850.04 2865,3850 2865,3830 3830,3830 3830,10 10,10 10,3830 2455,3830 2455,3850 -10,3850
  region net COM2: 30.75,455 578.58,455 654.51,530.93 1415.87,530.93 1435,511.8 1435,398.54 1421.46,385 663.57,385 613.58,335 35,335 20,350 20,444.25
  region net OPEN2: 33,675 525,675 625,775 865,775 875,765 875,625 865,615 625,615 545,535 33,535 22,546 22,664
  region net CLOSE2: 650,255 700,305 862.6,305 875,292.6 875,155 865,145 34,145 21.5,157.51 21.5,245 31.5,255
Multi-Layer:
  pour cut-out: 1825.99,3830 1975,3830 1975,2750 3000,2750 3000,2650 1825.99,2650
  pour cut-out: 1875,2650 1825,2650 1825,2120.49 1975,2120.49 1975,2650
  pour cut-out: 10,2225 665,2225 665,1625 1441.2,1625 1441.2,1575 590.98,1575 590.98,2175 10,2175
  pour cut-out: 3830,2285 3830,2215 3175,2215 3175,2650 3000,2650 3000,3830 3100,3830 3100,2750 3275,2750 3275,2285

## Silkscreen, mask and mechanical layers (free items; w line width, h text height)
Top Overlay:
  drawing of 802 lines, arcs and shapes, not listed
  text "-" at 428.14,3676.01 h393.7
  text "-" at 3184.05,3676.01 h393.7
  text "FEMALE" at 713.57,3538.02 h70.87 r270
  text "FEMALE" at 3108.57,3121.02 h70.87 r90
  text "+BAT" at -28.14,2973.54 h157.48
  text "+SOLAR" at 3456.86,2970.54 h118.11
  text "+" at 546.25,2859.65 h196.85 r90
  text "+" at 3384.84,2859.08 h196.85 r90
  text "SENSOR NODE / V3.1" at 2628.27,2724.78 h47.24
  text "-" at 546.25,2455.54 h275.59 r90
  text "-" at 556.09,2455.54 h275.59 r90
  text "-" at 3384.84,2455.54 h275.59 r90
  text "RESET" at 1091.24,2343.8 h31.5
  text "T1" at 457.69,2124.02 h31.5 r90
  text "T1" at 1539.86,2071.93 h31.5 r90
  text "G" at 1916.24,1033.93 h31.5 r90
  text "TX" at 1919.24,922.93 h31.5 r90
  text "RX" at 1919.24,818.93 h31.5 r90
Bottom Overlay:
  drawing of 873 lines, arcs and shapes, not listed
  text "SENSOR NODE V3.1 / Model: MultiSensor_LR433.1W / QTech Vietnam / 09/2019 / fps.qtechvietnam@gmail.com" at 2038.13,2921.65 h39.37
  text "CONNECTOR MAPPING" at 1510.95,1579.56 h39.37
  text "DS 01" at 1392.83,1490.97 h39.37
  text "1" at 1510.82,1490.97 h39.37
  text "SOLDER JUMP" at 2603.34,1490.97 h35.43
  text "TEST POINT" at 3016.72,1490.97 h39.37
  text "Back side" at 782.47,1431.92 h39.37
  text "DS 02" at 1392.83,1412.23 h39.37
  text "2" at 1510.82,1412.23 h39.37
  text "J7" at 2583.65,1412.23 h39.37
  text "VCC" at 2819.87,1412.23 h39.37
  text "T1" at 2997.04,1412.23 h39.37
  text "Wind Direction" at 1392.83,1333.49 h39.37
  text "3" at 1510.95,1333.49 h39.37
  text "J8" at 2583.65,1333.49 h39.37
  text "VBAT" at 2839.56,1333.49 h39.37
  text "T2" at 2997.04,1333.49 h39.37
  text "Enable Prog." at 2455.7,1323.65 h39.37
  text "Wind Speed" at 1392.83,1254.75 h39.37
  text "4" at 1510.95,1254.75 h39.37
  text "Dis. Q1" at 2465.54,1254.75 h39.37
  text "J11" at 2603.34,1254.75 h39.37
  text "VSEN" at 2839.56,1254.75 h39.37
  text "T4" at 2997.04,1254.75 h39.37
  text "8" at 1757.01,1244.91 h118.11
  text "Water Pressure" at 1392.83,1176.01 h39.37
  text "5" at 1510.95,1176.01 h39.37
  text "LED OFF" at 2475.39,1176.01 h39.37
  text "J12" at 2603.34,1176.01 h39.37
  text "VSOLAR" at 2869.09,1176.01 h39.37
  text "T5" at 2997.04,1176.01 h39.37
  text "1" at 782.6,1166.17 h118.11
  text "Air Pressure" at 1392.83,1097.27 h39.37
  text "6" at 1510.95,1097.27 h39.37
  text "GND" at 2819.87,1097.27 h39.37
  text "T6" at 2997.04,1097.27 h39.37
  text "Manual" at 2327.87,1038.59 h39.37
  text "SHT30 Soil" at 1392.83,1018.53 h39.37
  text "7" at 1510.95,1018.53 h39.37
  text "BUTTON" at 2701.76,998.85 h47.24
  text "SHT30 Humidity" at 1392.83,939.79 h39.37
  text "8" at 1510.95,939.79 h39.37
  text "2" at 782.6,920.11 h118.11
  text "7" at 1757.01,920.11 h118.11
  text "RESET" at 2918.3,920.11 h39.37
  text "3" at 959.76,744.99 h118.11
  text "4" at 1205.83,744.99 h118.11
  text "5" at 1451.89,744.99 h118.11
  text "6" at 1697.95,744.99 h118.11
  text "Front side" at 2908.46,674.04 h39.37
  text "INPUT Voltage range (BAT Connector) : 8-30V DC / INPUT SOLAR : Use SOLAR CHARGER board" at 2258.85,565.78 h39.37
